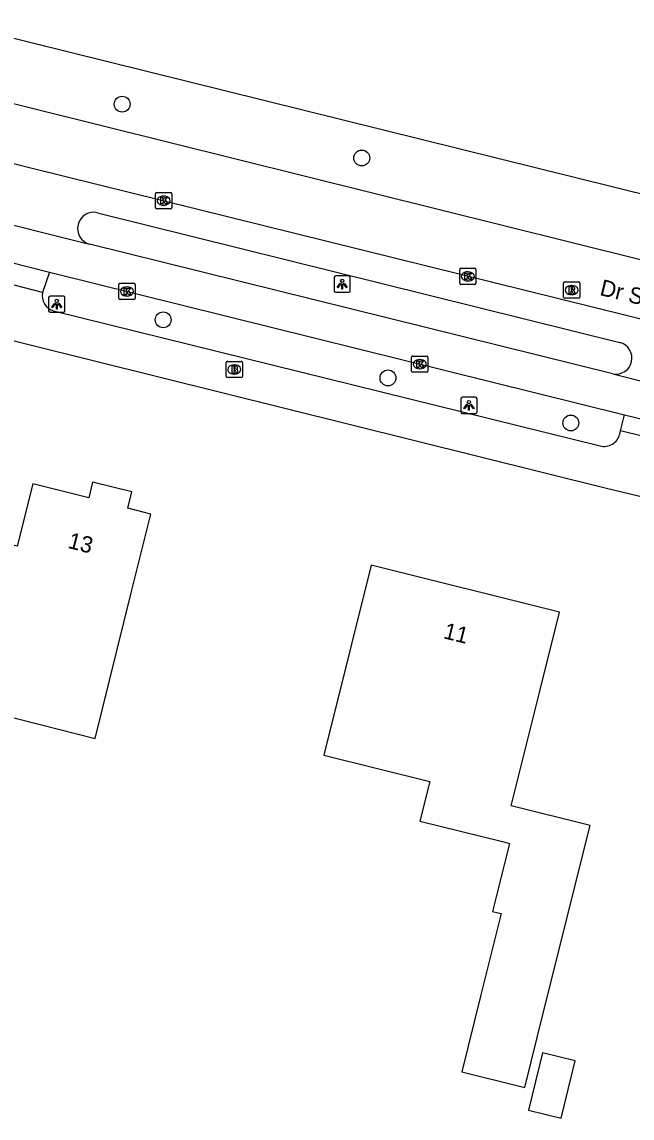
# Model space of a CAD drawing. Extents: x 161141 to 161601, y 381708 to 382245.
# Drawn here: x 161422 to 161459.5, y 382129.6 to 382197 of the extents above; entities that cross this region are included whole.
import ezdxf

# ---------------------------------------------------------------- set-up
doc = ezdxf.new("R2010")
doc.units = 0
for name, color, linetype in [('IMGEO_Boom', 7, 'Continuous'), ('IMGEO_Brandkraan', 7, 'Continuous'), ('IMGEO_Fietspad_gesloten', 7, 'Continuous'), ('IMGEO_Kolk', 7, 'Continuous'), ('IMGEO_Lichtpunt', 7, 'Continuous'), ('IMGEO_Openbare_ruimte_label', 7, 'Continuous'), ('IMGEO_Pand', 7, 'Continuous'), ('IMGEO_Pand_nummerreeks', 7, 'Continuous'), ('IMGEO_Parkeervlak_open', 7, 'Continuous'), ('IMGEO_Rijbaan_lokaal_gesloten', 7, 'Continuous'), ('IMGEO_Rioolput', 7, 'Continuous'), ('IMGEO_Voetpad_open', 7, 'Continuous')]:
    doc.layers.add(name, color=color, linetype=linetype)

msp = doc.modelspace()

# ---------------------------------------------------------------- linework, layer by layer
at = {"layer": 'IMGEO_Boom'}
for centre in [(161428.146, 382191.907), (161442.864, 382188.6), (161430.663, 382178.649), (161444.474, 382175.079), (161455.709, 382172.312)]:
    msp.add_circle(centre, 0.489, dxfattribs=at)
at = {"layer": 'IMGEO_Brandkraan'}
for p, q in [((161434.533, 382175.174), (161434.533, 382176.026)), ((161434.608, 382176.1), (161435.46, 382176.1)), ((161435.021, 382175.88), (161435.046, 382175.88)), ((161435.534, 382176.026), (161435.534, 382175.174)), ((161435.46, 382175.1), (161434.608, 382175.1)), ((161435.044, 382175.32), (161435.019, 382175.32))]:
    msp.add_line(p, q, dxfattribs=at)
for points in [[(161434.533, 382175.174), (161434.533, 382176.026)], [(161434.608, 382176.1), (161435.46, 382176.1)], [(161434.881, 382175.8), (161434.881, 382175.4), (161435.094, 382175.4)], [(161435.112, 382175.8), (161434.881, 382175.8)], [(161435.06, 382175.719), (161435.006, 382175.719), (161435.006, 382175.643)], [(161435.006, 382175.643), (161435.059, 382175.643)], [(161435.534, 382176.026), (161435.534, 382175.174)], [(161435.46, 382175.1), (161434.608, 382175.1)], [(161435.068, 382175.567), (161435.006, 382175.567), (161435.006, 382175.486)], [(161435.006, 382175.486), (161435.068, 382175.486)]]:
    msp.add_lwpolyline(points, dxfattribs=at)
for centre, radius, start, end in [((161434.61, 382176.024), 0.0765, 91.55205, 178.44795), ((161434.61, 382176.024), 0.0765, 91.55205, 178.44795), ((161435.061, 382175.681), 0.0379, 267.82845, 90.93552), ((161435.116, 382175.655), 0.145, 59.4692, 91.53667), ((161435.141, 382175.702), 0.0922, 285.51372, 58.15012), ((161435.146, 382175.51), 0.105, 301.31148, 78.98903), ((161435.458, 382176.024), 0.0765, 1.55205, 88.44795), ((161435.458, 382176.024), 0.0765, 1.55205, 88.44795), ((161434.61, 382175.176), 0.0765, 181.55205, 268.44795), ((161434.61, 382175.176), 0.0765, 181.55205, 268.44795), ((161435.069, 382175.526), 0.0404, 269.87594, 90.50774), ((161435.1, 382175.651), 0.251, 268.66757, 293.53466), ((161435.458, 382175.176), 0.0765, 271.55205, 358.44795), ((161435.458, 382175.176), 0.0765, 271.55205, 358.44795)]:
    msp.add_arc(centre, radius, start, end, dxfattribs=at)
for centre, major_axis, ratio, start_param, end_param in [((161435.02, 382175.6), (-0.387, 0.002), 0.722429, 4.712389, 7.853982), ((161435.045, 382175.6), (-0.39, 0.002), 0.717154, 1.570796, 4.712389)]:
    msp.add_ellipse(centre, major_axis=major_axis, ratio=ratio, start_param=start_param, end_param=end_param, dxfattribs=at)
at = {"layer": 'IMGEO_Fietspad_gesloten'}
for points in [[(161418.85, 382185.12), (161426.145, 382183.304)], [(161458.283, 382175.333), (161426.145, 382183.304)], [(161420.035, 382182.5), (161423.68, 382181.579)], [(161423.68, 382181.579), (161459.001, 382172.814)], [(161458.283, 382175.333), (161465.508, 382173.515)], [(161459.001, 382172.814), (161463.49, 382171.731)]]:
    msp.add_lwpolyline(points, dxfattribs=at)
at = {"layer": 'IMGEO_Kolk'}
for p, q in [((161430.192, 382185.548), (161430.192, 382186.4)), ((161430.267, 382186.474), (161431.119, 382186.474)), ((161431.193, 382186.4), (161431.193, 382185.548)), ((161430.68, 382186.254), (161430.705, 382186.254)), ((161431.119, 382185.474), (161430.267, 382185.474)), ((161430.703, 382185.694), (161430.678, 382185.694)), ((161448.879, 382180.896), (161448.879, 382181.748)), ((161448.954, 382181.822), (161449.806, 382181.822)), ((161449.88, 382181.748), (161449.88, 382180.896)), ((161449.39, 382181.042), (161449.365, 382181.042)), ((161449.367, 382181.602), (161449.392, 382181.602)), ((161427.94, 382179.97), (161427.94, 382180.822)), ((161428.015, 382180.896), (161428.867, 382180.896)), ((161428.428, 382180.676), (161428.453, 382180.676)), ((161428.941, 382180.822), (161428.941, 382179.97)), ((161449.806, 382180.822), (161448.954, 382180.822)), ((161428.867, 382179.896), (161428.015, 382179.896)), ((161428.451, 382180.116), (161428.426, 382180.116)), ((161445.925, 382175.502), (161445.925, 382176.354)), ((161446, 382176.428), (161446.852, 382176.428)), ((161446.926, 382176.354), (161446.926, 382175.502)), ((161446.436, 382175.648), (161446.411, 382175.648)), ((161446.413, 382176.208), (161446.438, 382176.208)), ((161446.852, 382175.428), (161446, 382175.428))]:
    msp.add_line(p, q, dxfattribs=at)
for points in [[(161430.192, 382185.548), (161430.192, 382186.4)], [(161430.267, 382186.474), (161431.119, 382186.474)], [(161431.193, 382186.4), (161431.193, 382185.548)], [(161430.513, 382186.174), (161430.636, 382186.174), (161430.636, 382186.023), (161430.766, 382186.174), (161430.93, 382186.174), (161430.784, 382186.023), (161430.937, 382185.774), (161430.785, 382185.774), (161430.7, 382185.938), (161430.636, 382185.871), (161430.636, 382185.774), (161430.513, 382185.774), (161430.513, 382186.174)], [(161431.119, 382185.474), (161430.267, 382185.474)], [(161448.879, 382180.896), (161448.879, 382181.748)], [(161448.954, 382181.822), (161449.806, 382181.822)], [(161449.88, 382181.748), (161449.88, 382180.896)], [(161449.2, 382181.522), (161449.323, 382181.522), (161449.323, 382181.371), (161449.453, 382181.522), (161449.617, 382181.522), (161449.471, 382181.371), (161449.624, 382181.122), (161449.472, 382181.122), (161449.387, 382181.286), (161449.323, 382181.219), (161449.323, 382181.122), (161449.2, 382181.122), (161449.2, 382181.522)], [(161427.94, 382179.97), (161427.94, 382180.822)], [(161428.015, 382180.896), (161428.867, 382180.896)], [(161428.261, 382180.596), (161428.384, 382180.596), (161428.384, 382180.445), (161428.514, 382180.596), (161428.678, 382180.596), (161428.532, 382180.445), (161428.685, 382180.196), (161428.533, 382180.196), (161428.448, 382180.36), (161428.384, 382180.293), (161428.384, 382180.196), (161428.261, 382180.196), (161428.261, 382180.596)], [(161428.941, 382180.822), (161428.941, 382179.97)], [(161449.806, 382180.822), (161448.954, 382180.822)], [(161428.867, 382179.896), (161428.015, 382179.896)], [(161445.925, 382175.502), (161445.925, 382176.354)], [(161446, 382176.428), (161446.852, 382176.428)], [(161446.926, 382176.354), (161446.926, 382175.502)], [(161446.246, 382176.128), (161446.369, 382176.128), (161446.369, 382175.977), (161446.499, 382176.128), (161446.663, 382176.128), (161446.517, 382175.977), (161446.67, 382175.728), (161446.518, 382175.728), (161446.433, 382175.892), (161446.369, 382175.825), (161446.369, 382175.728), (161446.246, 382175.728), (161446.246, 382176.128)], [(161446.852, 382175.428), (161446, 382175.428)]]:
    msp.add_lwpolyline(points, dxfattribs=at)
for centre, start, end in [((161430.269, 382186.398), 91.55205, 178.44795), ((161430.269, 382186.398), 91.55205, 178.44795), ((161431.117, 382186.398), 1.55205, 88.44795), ((161431.117, 382186.398), 1.55205, 88.44795), ((161430.269, 382185.55), 181.55205, 268.44795), ((161430.269, 382185.55), 181.55205, 268.44795), ((161431.117, 382185.55), 271.55205, 358.44795), ((161431.117, 382185.55), 271.55205, 358.44795), ((161448.956, 382181.746), 91.55205, 178.44795), ((161448.956, 382181.746), 91.55205, 178.44795), ((161449.804, 382181.746), 1.55205, 88.44795), ((161449.804, 382181.746), 1.55205, 88.44795), ((161428.017, 382180.82), 91.55205, 178.44795), ((161428.017, 382180.82), 91.55205, 178.44795), ((161428.865, 382180.82), 1.55205, 88.44795), ((161428.865, 382180.82), 1.55205, 88.44795), ((161448.956, 382180.898), 181.55205, 268.44795), ((161448.956, 382180.898), 181.55205, 268.44795), ((161449.804, 382180.898), 271.55205, 358.44795), ((161449.804, 382180.898), 271.55205, 358.44795), ((161428.017, 382179.972), 181.55205, 268.44795), ((161428.017, 382179.972), 181.55205, 268.44795), ((161428.865, 382179.972), 271.55205, 358.44795), ((161428.865, 382179.972), 271.55205, 358.44795), ((161446.002, 382176.352), 91.55205, 178.44795), ((161446.002, 382176.352), 91.55205, 178.44795), ((161446.85, 382176.352), 1.55205, 88.44795), ((161446.85, 382176.352), 1.55205, 88.44795), ((161446.002, 382175.504), 181.55205, 268.44795), ((161446.002, 382175.504), 181.55205, 268.44795), ((161446.85, 382175.504), 271.55205, 358.44795), ((161446.85, 382175.504), 271.55205, 358.44795)]:
    msp.add_arc(centre, 0.0765, start, end, dxfattribs=at)
for centre, major_axis, ratio, start_param, end_param in [((161430.679, 382185.974), (-0.387, 0.002), 0.722429, 4.712389, 7.853982), ((161430.704, 382185.974), (-0.39, 0.002), 0.717154, 1.570796, 4.712389), ((161449.366, 382181.322), (-0.387, 0.002), 0.722429, 4.712389, 7.853982), ((161449.391, 382181.322), (-0.39, 0.002), 0.717154, 1.570796, 4.712389), ((161428.427, 382180.396), (-0.387, 0.002), 0.722429, 4.712389, 7.853982), ((161428.452, 382180.396), (-0.39, 0.002), 0.717154, 1.570796, 4.712389), ((161446.412, 382175.928), (-0.387, 0.002), 0.722429, 4.712389, 7.853982), ((161446.437, 382175.928), (-0.39, 0.002), 0.717154, 1.570796, 4.712389)]:
    msp.add_ellipse(centre, major_axis=major_axis, ratio=ratio, start_param=start_param, end_param=end_param, dxfattribs=at)
at = {"layer": 'IMGEO_Lichtpunt'}
for p, q in [((161441.162, 382181.251), (161441.162, 382180.444)), ((161441.162, 382181.251), (161441.162, 382180.444)), ((161442.064, 382181.346), (161441.256, 382181.346)), ((161442.064, 382181.346), (161441.256, 382181.346)), ((161442.158, 382180.444), (161442.158, 382181.251)), ((161442.158, 382180.444), (161442.158, 382181.251)), ((161441.256, 382180.35), (161442.064, 382180.35)), ((161441.256, 382180.35), (161442.064, 382180.35)), ((161423.629, 382180.019), (161423.629, 382179.212)), ((161423.629, 382180.019), (161423.629, 382179.212)), ((161424.531, 382180.114), (161423.723, 382180.114)), ((161424.531, 382180.114), (161423.723, 382180.114)), ((161424.625, 382179.212), (161424.625, 382180.019)), ((161424.625, 382179.212), (161424.625, 382180.019)), ((161423.723, 382179.118), (161424.531, 382179.118)), ((161423.723, 382179.118), (161424.531, 382179.118)), ((161448.948, 382173.798), (161448.948, 382172.991)), ((161448.948, 382173.798), (161448.948, 382172.991)), ((161449.85, 382173.893), (161449.042, 382173.893)), ((161449.85, 382173.893), (161449.042, 382173.893)), ((161449.944, 382172.991), (161449.944, 382173.798)), ((161449.944, 382172.991), (161449.944, 382173.798)), ((161449.042, 382172.897), (161449.85, 382172.897)), ((161449.042, 382172.897), (161449.85, 382172.897))]:
    msp.add_line(p, q, dxfattribs=at)
for points in [[(161441.536, 382180.915), (161441.575, 382180.887), (161441.387, 382180.625), (161441.349, 382180.652), (161441.536, 382180.915)], [(161441.638, 382180.867), (161441.685, 382180.867), (161441.685, 382180.545), (161441.638, 382180.545), (161441.638, 382180.867)], [(161441.748, 382180.887), (161441.786, 382180.914), (161441.973, 382180.652), (161441.934, 382180.624), (161441.748, 382180.887)], [(161424.003, 382179.683), (161424.042, 382179.655), (161423.854, 382179.393), (161423.816, 382179.42), (161424.003, 382179.683)], [(161424.215, 382179.655), (161424.253, 382179.682), (161424.44, 382179.42), (161424.401, 382179.392), (161424.215, 382179.655)], [(161424.105, 382179.635), (161424.152, 382179.635), (161424.152, 382179.313), (161424.105, 382179.313), (161424.105, 382179.635)], [(161449.322, 382173.462), (161449.361, 382173.434), (161449.173, 382173.172), (161449.135, 382173.199), (161449.322, 382173.462)], [(161449.424, 382173.414), (161449.471, 382173.414), (161449.471, 382173.092), (161449.424, 382173.092), (161449.424, 382173.414)], [(161449.534, 382173.434), (161449.572, 382173.461), (161449.759, 382173.199), (161449.72, 382173.171), (161449.534, 382173.434)]]:
    msp.add_lwpolyline(points, dxfattribs=at)
for centre in [(161441.661, 382181.049), (161424.128, 382179.817), (161449.447, 382173.596)]:
    msp.add_circle(centre, 0.0994, dxfattribs=at)
for centre, start, end in [((161441.256, 382181.251), 90, 180), ((161441.256, 382181.251), 90, 180), ((161442.064, 382181.251), 0, 90), ((161442.064, 382181.251), 0, 90), ((161441.256, 382180.444), 180, 270), ((161441.256, 382180.444), 180, 270), ((161442.064, 382180.444), 270, 0), ((161442.064, 382180.444), 270, 360), ((161423.723, 382180.019), 90, 180), ((161423.723, 382180.019), 90, 180), ((161424.531, 382180.019), 0, 90), ((161424.531, 382180.019), 0, 90), ((161423.723, 382179.212), 180, 270), ((161423.723, 382179.212), 180, 270), ((161424.531, 382179.212), 270, 0), ((161424.531, 382179.212), 270, 360), ((161449.042, 382173.798), 90, 180), ((161449.042, 382173.798), 90, 180), ((161449.85, 382173.798), 0, 90), ((161449.85, 382173.798), 0, 90), ((161449.042, 382172.991), 180, 270), ((161449.042, 382172.991), 180, 270), ((161449.85, 382172.991), 270, 0), ((161449.85, 382172.991), 270, 360)]:
    msp.add_arc(centre, 0.0946, start, end, dxfattribs=at)
at = {"layer": 'IMGEO_Pand'}
for points in [[(161428.705, 382161.861), (161429.913, 382166.712), (161428.484, 382167.068), (161428.734, 382168.071), (161426.329, 382168.67), (161426.089, 382167.707), (161422.647, 382168.564), (161421.693, 382164.734), (161420.44, 382165.046), (161418.18, 382155.968), (161413.467, 382157.169), (161412.259, 382152.318), (161410.912, 382146.912), (161417.202, 382145.309), (161419.537, 382154.683), (161426.476, 382152.914), (161428.705, 382161.861)], [(161453.805, 382155.828), (161455.013, 382160.679), (161443.433, 382163.562), (161442.225, 382158.711), (161440.526, 382151.889), (161447.045, 382150.266), (161446.44, 382147.835), (161451.502, 382146.575), (161451.929, 382146.469), (161450.889, 382142.291), (161451.237, 382142.204), (161451.423, 382142.158), (161451.402, 382142.074), (161450.157, 382137.072), (161449.001, 382132.427), (161452.882, 382131.461), (161454.038, 382136.105), (161456.893, 382147.575), (161452.051, 382148.781), (161453.805, 382155.828)], [(161453.11, 382130.071), (161455.111, 382129.583), (161455.97, 382133.103), (161453.969, 382133.591), (161453.11, 382130.071)]]:
    msp.add_lwpolyline(points, dxfattribs=at)
at = {"layer": 'IMGEO_Parkeervlak_open'}
msp.add_lwpolyline([(161426.637, 382185.233), (161458.715, 382177.254)], dxfattribs=at)
for centre, radius, start, end in [((161426.396, 382184.267), 0.995, 76.00624, 255.3768), ((161458.479, 382176.298), 0.985, 258.5026, 76.14941)]:
    msp.add_arc(centre, radius, start, end, dxfattribs=at)
at = {"layer": 'IMGEO_Rijbaan_lokaal_gesloten'}
for points in [[(161417.456, 382196.964), (161420.058, 382196.306), (161460.894, 382186.197), (161500, 382176.547), (161558.491, 382162.113), (161560.838, 382161.565), (161562.428, 382161.253), (161571.347, 382159.936), (161575.364, 382159.517)], [(161416.542, 382193.184), (161418.72, 382192.635), (161459.898, 382182.379), (161500, 382172.465), (161568.862, 382155.44)], [(161571.771, 382151.019), (161502.587, 382168.125), (161500, 382168.766), (161459.102, 382178.908), (161420.449, 382188.487), (161415.442, 382189.785), (161412.878, 382190.505)]]:
    msp.add_lwpolyline(points, dxfattribs=at)
at = {"layer": 'IMGEO_Rioolput'}
for p, q in [((161455.257, 382180.054), (161455.257, 382180.906)), ((161455.332, 382180.98), (161456.184, 382180.98)), ((161455.745, 382180.76), (161455.77, 382180.76)), ((161456.258, 382180.906), (161456.258, 382180.054)), ((161456.184, 382179.98), (161455.332, 382179.98)), ((161455.768, 382180.2), (161455.743, 382180.2))]:
    msp.add_line(p, q, dxfattribs=at)
for points in [[(161455.257, 382180.054), (161455.257, 382180.906)], [(161455.332, 382180.98), (161456.184, 382180.98)], [(161455.846, 382180.678), (161455.594, 382180.68), (161455.594, 382180.28)], [(161455.594, 382180.28), (161455.718, 382180.28), (161455.718, 382180.442), (161455.729, 382180.442)], [(161455.772, 382180.599), (161455.718, 382180.599), (161455.718, 382180.518)], [(161455.718, 382180.518), (161455.77, 382180.518)], [(161455.776, 382180.413), (161455.847, 382180.28), (161455.987, 382180.28), (161455.922, 382180.406)], [(161456.258, 382180.906), (161456.258, 382180.054)], [(161456.184, 382179.98), (161455.332, 382179.98)]]:
    msp.add_lwpolyline(points, dxfattribs=at)
for centre, radius, start, end in [((161455.334, 382180.904), 0.0765, 91.55205, 178.44795), ((161455.334, 382180.904), 0.0765, 91.55205, 178.44795), ((161455.728, 382180.389), 0.0533, 26.02933, 88.69889), ((161455.754, 382180.707), 0.19, 274.7715, 282.96867), ((161455.778, 382180.503), 0.0964, 77.00612, 93.18647), ((161455.792, 382180.56), 0.0378, 276.66336, 79.67722), ((161455.845, 382180.568), 0.109, 350.36119, 89.41601), ((161455.843, 382180.568), 0.112, 277.58423, 350.98172), ((161455.827, 382180.353), 0.108, 29.51342, 73.79051), ((161456.182, 382180.904), 0.0765, 1.55205, 88.44795), ((161456.182, 382180.904), 0.0765, 1.55205, 88.44795), ((161455.334, 382180.056), 0.0765, 181.55205, 268.44795), ((161455.334, 382180.056), 0.0765, 181.55205, 268.44795), ((161456.182, 382180.056), 0.0765, 271.55205, 358.44795), ((161456.182, 382180.056), 0.0765, 271.55205, 358.44795)]:
    msp.add_arc(centre, radius, start, end, dxfattribs=at)
for centre, major_axis, ratio, start_param, end_param in [((161455.744, 382180.48), (-0.387, 0.002), 0.722429, 4.712389, 7.853982), ((161455.769, 382180.48), (-0.39, 0.002), 0.717154, 1.570796, 4.712389)]:
    msp.add_ellipse(centre, major_axis=major_axis, ratio=ratio, start_param=start_param, end_param=end_param, dxfattribs=at)
at = {"layer": 'IMGEO_Voetpad_open'}
for points in [[(161387.058, 382185.651), (161389.844, 382185.251), (161418.52, 382178.097), (161457.897, 382168.303), (161477.956, 382163.494), (161500, 382158.072), (161544.61, 382147.101), (161553.295, 382144.911), (161577.621, 382138.939), (161579.137, 382138.37)], [(161423.245, 382180.339), (161420.225, 382181.103)], [(161423.68, 382181.579), (161423.245, 382180.339)], [(161423.927, 382179.199), (161457.504, 382170.904)], [(161458.766, 382171.826), (161459.001, 382172.814)], [(161458.712, 382171.632), (161458.766, 382171.826)], [(161463.163, 382170.733), (161458.766, 382171.826)]]:
    msp.add_lwpolyline(points, dxfattribs=at)
for centre, radius, start, end in [((161424.267, 382180.176), 1.035, 170.95924, 250.82034), ((161457.752, 382171.859), 0.987, 255.46401, 346.68644)]:
    msp.add_arc(centre, radius, start, end, dxfattribs=at)

# ---------------------------------------------------------------- texts
at = {"layer": 'IMGEO_Openbare_ruimte_label'}
msp.add_text('Dr Schaepmanlaan', height=1, rotation=346.35276, dxfattribs=at).set_placement((161457.435, 382180.183))
at = {"layer": 'IMGEO_Pand_nummerreeks'}
for s, rotation, p in [('13', 345.70059, (161424.757, 382164.642)), ('11', 346.01983, (161447.827, 382159.087))]:
    msp.add_text(s, height=1, rotation=rotation, dxfattribs=at).set_placement(p)

doc.saveas('drawing.dxf')
